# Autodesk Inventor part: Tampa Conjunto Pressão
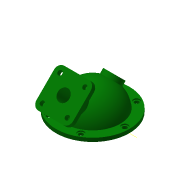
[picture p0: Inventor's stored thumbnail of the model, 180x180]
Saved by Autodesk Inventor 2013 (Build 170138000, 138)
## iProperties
Manager: Liga de aço
Category: Ø100mm - 60mm
Company: YouTube Montagens e Serviços LTDA
Created: 2013-08
Part Number: Tampa Conjunto Pressão
Material: Liga de aço
Document SubType Name: Modeling
Designer: Draw
Density: 7.85 g/cm^3
Mass: 658.021 g
Surface Area: 324.905 cm^2
Volume: 83.8243 cm^3
Engineer: 1:1
Project: Prof. Daniel Severino
Semelhante: 006.10/2012 - D
Title: CARCAÇA
Revision Number: 01/A
Author: Cristiano Oliveira
Comments: 002.16/2013 - A
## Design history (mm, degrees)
sketch "Esboço1"
  geometry: L1 (0, 38)-(0, 32); L2 (32, 0)-(50, 0); L3 (37.67, 5)-(50, 5); L4 (50, 0)-(50, 5); A1 r 32 centre (0, 0) between (32, 0) and (0, 32); A2 r 38 centre (0, 0) between (37.67, 5) and (0, 38); 1 further point
  constraints: 8 end point, 4 point on circle, 2 centre point, 2 coincident, 2 perpendicular, 1 parallel, 1 vertical
  dimensions: "d0" = 64 diameter of A1; "d1" = 76 diameter of A2; "d2" = 5 distance between parallel lines of L2 L3; "d3" = 50 distance of A2.centre L2.end
revolve "Revolução1" sketch "Esboço1" stored, may be unused: angle "d4" = 90 deg
node "Plano de trabalho2"
  node "Plano de trabalho1"
sketch "Esboço2"
  geometry: C1 r 12.5 at (0, 0); 1 further point
  constraints: 1 centre point, 1 coincident
  dimensions: "d7" = 25 diameter of C1
extrude "Extrusão1" join sketch "Esboço2" stored distance "d9" = 30; taper "d10" = 0 deg
sketch "Esboço3"
  geometry: 1 further point
hole "Furo1" sketch "Esboço3" at (0, 0) diameter "d11" = 13.835; stored, may be unused: countersink angle "d15" = 90 deg, drill point angle "d17" = 118 deg; dims "d12" = 20, "d13" = 4, "d14" = 2, "d16" = 8
node "Plano de trabalho4"
  node "Plano de trabalho3"
sketch "Esboço4"
  geometry: C1 r 16 at (0, 0); 1 further point
  constraints: 1 centre point, 1 coincident
  dimensions: "d20" = 32 diameter of C1
extrude "Extrusão2" join sketch "Esboço4" stored distance "d21" = 10; taper "d22" = 0 deg
sketch "Esboço5"
  geometry: L1 (-25, -25)-(25, -25); L2 (25, -25)-(25, 25); L3 (25, 25)-(-25, 25); L4 (-25, 25)-(-25, -25); L5 (-25, -25)-(25, 25); L6 (25, -25)-(-25, 25); C1 r 16 at (0, 0) reference
  constraints: 12 end point, 2 midpoint, 2 parallel, 1 horizontal, 1 perpendicular
  dimensions: "d23" = 50 distance of L3.end L2.end; "d24" = 50 distance of L2.end L1.end
extrude "Extrusão3" join sketch "Esboço5" distance "d25" = 6; taper "d26" = 0 deg
sketch "Esboço6"
  geometry: 1 further point
hole "Furo2" sketch "Esboço6" at (0, 0) diameter "d27" = 16; stored, may be unused: countersink angle "d31" = 90 deg, drill point angle "d33" = 118 deg; dims "d28" = 6, "d29" = 4, "d30" = 2, "d32" = 8
fillet "Arredondamento1" dims "d34" = 8
sketch "Esboço7"
  geometry: C1 r 3 at (-17, 17); C2 r 3 at (17, 17); C3 r 3 at (-17, -17); C4 r 3 at (17, -17); A1 r 8 centre (-17, -17) between (-25, -17) and (-17, -25) reference; A2 r 8 centre (17, -17) between (17, -25) and (25, -17) reference; A3 r 8 centre (17, 17) between (25, 17) and (17, 25) reference; A4 r 8 centre (-17, 17) between (-17, 25) and (-25, 17) reference
  constraints: 4 centre point, 4 coincident
  dimensions: "d35" = 6 diameter of C1; "d36" = 6 diameter of C2; "d37" = 6 diameter of C3; "d38" = 6 diameter of C4
extrude "Extrusão4" cut sketch "Esboço7" stored distance "d39" = 6; taper "d40" = 0 deg
sketch "Esboço8"
  geometry: L1 (-50, 0)-(-37.67, 0); 3 further points
  constraints: 2 end point, 2 horizontal alignment, 1 horizontal, 1 midpoint, 2 other
hole "Furo3" sketch "Esboço8" at (-43.835, 0) diameter "d41" = 6; stored, may be unused: countersink angle "d45" = 90 deg, drill point angle "d47" = 118 deg; dims "d42" = 6, "d43" = 9, "d44" = 1.5, "d46" = 8
pattern_circular "Padrão circular1" dims angle "d49" = 360 deg
sketch "Esboço9"
  geometry: C1 r 32 at (0, 0) reference; C2 r 50 at (0, 0) reference; C3 r 35 at (0, 0)
  constraints: 1 centre point, 1 coincident
  dimensions: "d51" = 70 diameter of C3
extrude "Extrusão5" join sketch "Esboço9" distance "d52" = 1.5; taper "d53" = 0 deg
node "Sólido1"
other parameters: "d5" = 45 deg, "d6" = 42, "d18" = -45 deg
